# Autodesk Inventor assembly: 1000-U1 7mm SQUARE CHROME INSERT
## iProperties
Created: 2007-03
Part Number: 1000-U1 7mm SQUARE CHROME INSERT
Document SubType Name: Assembly
Designer: Andy Moles
Translation Standard: STEP AP203
File Name: 1000-U01_ASM
Preprocessor: PRO/ENGINEER BY PARAMETRIC TECHNOLOGY CORPORATION, 2001390
Postprocessor: Build: 344b, Release: 11 SP2 - Date: Fri 08/18/2006
Sent Units: MILLIMETERS
Uncertainty: 0.0038507305871349996
Author: Andy Moles
